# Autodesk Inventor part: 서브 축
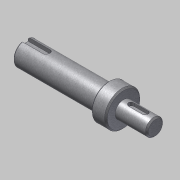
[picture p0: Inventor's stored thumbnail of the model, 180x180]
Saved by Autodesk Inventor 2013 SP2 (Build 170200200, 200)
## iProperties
Created: 2016-04
Part Number: 서브 축
Document SubType Name: Modeling
Designer: mdu
Density: 1 g/cm^3
Mass: 19.9624 g
Surface Area: 57.7178 cm^2
Volume: 19.9624 cm^3
Material: 강철, 연강
Author: mdu
Revision Number: 1
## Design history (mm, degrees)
sketch "스케치1"
  geometry: L1 (-16.331, 0)-(-108.831, 0); L2 (-16.331, 0)-(-16.331, -6); L3 (-16.331, -6)-(-38.831, -6); L4 (-38.831, -12.5)-(-46.5, -12.5); L5 (-46.5, -8.5)-(-108.831, -8.5); L6 (-108.831, -8.5)-(-108.831, 0); L7 (-46.5, -8.5)-(-46.5, -12.5); L8 (-38.831, -6)-(-38.831, -12.5); L9 (-46.5, 12.249)-(-46.5, -12.249) reference; L10 (-38.831, -17)-(-38.831, 17) reference; 2 further points
  constraints: 17 end point, 4 perpendicular, 2 collinear, 2 parallel, 1 horizontal, 1 midpoint, 1 point on line
  dimensions: "d1" = 12 diameter of L3 L1; "d2" = 25 diameter of L4 L1; "d3" = 17 diameter of L5 L1; "d18" = 22.5 distance of L2.end L3.end; "d20" = 70 distance between parallel lines of L6 L8; "d21" = 7.66872 distance of L4.start L4.end (derived)
revolve "회전1" sketch "스케치1" stored, may be unused: angle "d5" = 90 deg
chamfer "모따기1" distance "d6" = 1; stored, may be unused: second distance "d7" = 2, angle "d8" = 45 deg
node "작업 평면1"
sketch "스케치2"
  geometry: L1 (11.25, 5)-(11.25, -5) reference; L2 (-5.75, -2)-(4.25, -2); L3 (4.25, 2)-(-5.75, 2); A1 r 2 centre (4.25, 0) between (4.25, -2) and (4.25, 2); A2 r 2 centre (-5.75, 0) between (-5.75, 2) and (-5.75, -2); 2 further points
  constraints: 4 end point, 4 point on circle, 4 tangent, 2 centre point, 1 horizontal alignment, 1 midpoint, 1 parallel, 1 perpendicular
  dimensions: "d9" = 4 distance between parallel lines of L2 L3; "d10" = 14 dimension on A1 A2; "d11" = 5 distance edge to line of A1 L1
extrude "돌출1" cut sketch "스케치2" distance "d12" = 2.5; taper "d13" = 0 deg
node "작업 평면2"
sketch "스케치3"
  geometry: L1 (-31.166, -7.5)-(-31.166, 7.5) reference; L2 (-31.166, 2.5)-(-15.666, 2.5); L3 (-15.666, -2.5)-(-31.166, -2.5); A1 r 2.5 centre (-15.666, 0) between (-15.666, -2.5) and (-15.666, 2.5); 2 further points
  constraints: 4 end point, 2 perpendicular, 2 point on circle, 2 point on line, 2 tangent, 1 centre point, 1 horizontal alignment, 1 midpoint
  dimensions: "d14" = 5 distance between parallel lines of L3 L2; "d15" = 18 dimension on A1 L1
extrude "돌출2" cut sketch "스케치3" distance "d16" = 3; taper "d17" = 0 deg
sketch "스케치4"
  geometry: C1 r 12.5 at (0, 0) reference; 1 further point
extrude "돌출3" join sketch "스케치4" distance "d22" = 3; taper "d23" = 0 deg
chamfer "모따기2" distance "d24" = 1; stored, may be unused: second distance "d25" = 2, angle "d26" = 45 deg
node "솔리드1"
node "참조4"
node "참조5"
